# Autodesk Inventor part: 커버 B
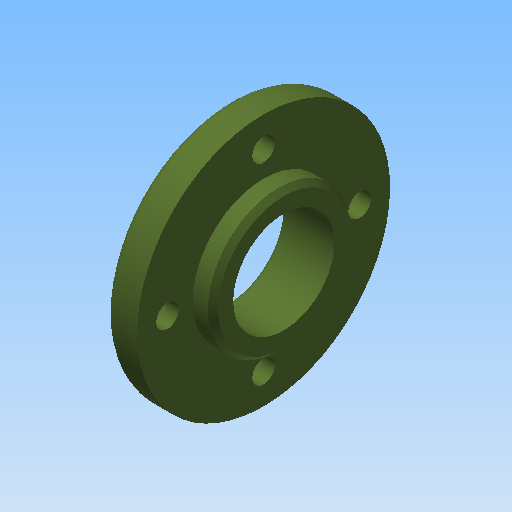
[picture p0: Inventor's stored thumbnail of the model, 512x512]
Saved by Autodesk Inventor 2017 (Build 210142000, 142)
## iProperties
Created: 2019-01
Part Number: 커버 B
Material: 알루미늄 6061
Document SubType Name: Modeling
Designer: mduedu
Density: 2.71 g/cm^3
Appearance: 올리브 녹색
Mass: 30.6342 g
Surface Area: 56.15 cm^2
Volume: 11.3041 cm^3
Author: mduedu
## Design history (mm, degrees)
sketch "스케치1"
  geometry: L1 (0, 0)-(7, 0); L2 (7, 0)-(7, 25); L3 (7, 25)-(0, 25); L4 (0, 25)-(0, 0); L5 (7, 0)-(11, 0); L6 (11, 0)-(11, 14); L7 (11, 14)-(7, 14); L8 (7, 14)-(7, 0)
  constraints: 16 end point, 4 parallel, 2 horizontal, 2 perpendicular
  dimensions: "d0" = 50 diameter of L3 L1; "d2" = 11 distance between parallel lines of L6 L4; "d3" = 7 distance of L2.end L3.end; "d4" = 28 diameter of L7 L5
revolve "회전1" sketch "스케치1" stored, may be unused: angle "d5" = 90 deg
sketch "스케치2"
  geometry: C1 r 10 at (0, 0); 1 further point
  constraints: 1 centre point, 1 coincident
  dimensions: "d6" = 20 diameter of C1
extrude "돌출1" cut sketch "스케치2" stored distance "d7" = 10; taper "d8" = 0 deg
chamfer "모따기1" distance "d9" = 1; stored, may be unused: second distance "d10" = 2, angle "d11" = 45 deg
fillet "모깎기1" dims "d12" = 3
sketch "스케치3" dims "d13" = 38
  geometry: 6 further points
  constraints: 2 vertical alignment, 1 coincident, 7 other
  dimensions: "d16" = 360 deg dimension on point (0, 0) point (0, 19) (derived)
chamfer "모따기2" distance "d18" = 1; stored, may be unused: second distance "d19" = 2, angle "d20" = 45 deg
sketch "스케치4"
  geometry: 4 further points
  constraints: 4 other
hole "구멍1" sketch "스케치4" at (-19, 0), (0, -19), (19, 0), (0, 19) diameter "d21" = 4.5; stored, may be unused: countersink angle "d25" = 90 deg, drill point angle "d27" = 0 deg; dims "d22" = 6, "d23" = 8, "d24" = 4.6, "d26" = 8
node "솔리드1"
